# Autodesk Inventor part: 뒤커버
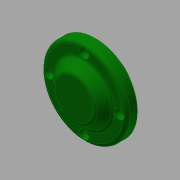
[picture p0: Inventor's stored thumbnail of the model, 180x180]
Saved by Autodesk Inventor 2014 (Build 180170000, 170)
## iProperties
Created: 2017-08
Part Number: 뒤커버
Material: 알루미늄 6061
Document SubType Name: Modeling
Designer: mduedu
Density: 1 g/cm^3
Appearance: Dark Green
Author: mduedu
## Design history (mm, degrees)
sketch "스케치1"
  geometry: C1 r 35 at (0, 0); 1 further point
  constraints: 1 centre point, 1 coincident
  dimensions: "d0" = 70 diameter of C1
extrude "돌출1" new body sketch "스케치1" distance "d1" = 10; taper "d2" = 0 deg
sketch "스케치2"
  geometry: C1 r 24 at (0, 0); 1 further point
  constraints: 1 centre point, 1 coincident
  dimensions: "d3" = 48 diameter of C1
node "작업 평면1"
sketch "스케치3"
  geometry: C1 r 17 at (0, 0); 1 further point
  constraints: 1 centre point, 1 coincident
  dimensions: "d5" = 34 diameter of C1
feature "로프트1" sketch "스케치3" dims "d6" = 0, "d7" = 90 deg, "d8" = 0, "d9" = 90 deg
sketch "스케치4"
  geometry: C1 r 24 at (0, 0) reference; 1 further point
extrude "돌출2" join sketch "스케치4" distance "d10" = 8; taper "d11" = 0 deg
hole "구멍1" diameter "d14" = 40; stored, may be unused: countersink angle "d18" = 90 deg, drill point angle "d20" = 0 deg; dims "d12" = 10, "d13" = 10, "d15" = 6, "d16" = 4, "d17" = 2, "d19" = 12
hole "구멍2" diameter "d23" = 34; stored, may be unused: countersink angle "d27" = 90 deg, drill point angle "d29" = 0 deg; dims "d24" = 6, "d25" = 4, "d26" = 2, "d28" = 6, "d62" = 10, "d63" = 10
chamfer "모따기1" distance "d39" = 1; stored, may be unused: second distance "d40" = 2, angle "d41" = 45 deg
fillet "모깎기1" dims "d42" = 0.3
fillet "모깎기2" dims "d43" = 3
sketch "스케치5" dims "d44" = 58
  geometry: 6 further points
  constraints: 2 vertical alignment, 1 coincident, 7 other
  dimensions: "d47" = 360 deg dimension on point (0, 0) point (0, 29) (derived)
sketch "스케치6"
  geometry: 4 further points
  constraints: 4 other
hole "구멍4" sketch "스케치6" at (0, 29), (-29, 0), (29, 0), (0, -29) diameter "d49" = 4.5; stored, may be unused: countersink angle "d53" = 90 deg, drill point angle "d55" = 0 deg; dims "d50" = 6, "d51" = 8, "d52" = 4.6, "d54" = 8
fillet "모깎기3" dims "d56" = 3
fillet "모깎기4" dims "d57" = 3
fillet "모깎기5" dims "d58" = 3
chamfer "모따기2" distance "d59" = 1; stored, may be unused: second distance "d60" = 2, angle "d61" = 45 deg
node "솔리드1"
other parameters: "d4" = 8
